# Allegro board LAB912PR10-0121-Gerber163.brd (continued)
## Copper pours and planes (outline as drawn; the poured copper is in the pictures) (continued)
SW_1.35VP on TOP: 61.84,41.3 64.64,41.3 64.89,41.04 64.89,33.1 64.38,32.6 59.81,32.6 59.62,32.79 59.62,37.99 59.81,38.18 61.72,38.18 61.78,38.25 61.78,41.23
SW_1.35VP on TOP: 59.33,49.04 60.09,49.04 60.3,48.83 60.3,48.75 60.7,48.34 60.7,46.19 60.64,46.12 60,46.12 59.94,46.19 59.94,47.65 59.23,48.35 59.23,48.95
UG_3V on TOP (solid shape): 37.2,46.31 37.2,46.12 36.19,45.11 35.55,45.11 35.43,45.23 35.43,45.61 36.19,46.38 37.14,46.38
UG_3V on TOP: 33.08,41.61 32.7,41.61 32.63,41.55 32.63,40.97 32.59,40.93 32.59,40.51 32.75,40.36 33.61,40.36 33.72,40.47 33.72,40.97
UG_3V on IN2: 32.63,41.55 32.63,40.34 32.74,40.24 33.51,40.24 33.71,40.43 33.71,41.68 33.65,41.74 32.82,41.74
UG_3V on IN2: 35.83,46.09 36.43,46.09 36.57,45.95 36.57,45.68 35.01,44.12 34.84,44.12 34.41,44.55 34.41,44.67
UG_5V on TOP (solid shape): 46.41,41.36 46.41,40.72 46.22,40.53 45.33,40.53 45.14,40.72 45.14,41.61 45.27,41.74 46.03,41.74
UG_5V on TOP: 40.65,45.55 40.52,45.42 39.69,45.42 39.5,45.61 39.5,45.99 39.38,46.12 39.38,46.3 39.45,46.38 40.29,46.38 40.65,46.02
UG_5V on IN2: 45.14,41.99 46.16,41.99 46.28,41.87 46.28,40.6 46.16,40.47 45.27,40.47 44.89,40.85 44.89,41.74
UG_5V on IN2: 41.32,46.15 41.48,45.98 41.48,45.31 41.31,45.13 40.75,45.13 40.37,45.51 39.48,45.51 39.41,45.57 39.41,45.89 39.67,46.15
UGATE1 on TOP: 135.06,135.21 135.12,135.28 135.12,136.74 135.06,136.8 133.98,136.8 133.91,136.74 133.91,135.28 133.98,135.21
UGATE1 on BOTTOM: 124.58,146.87 124.58,146.03 124.79,145.82 126.05,145.82 126.15,145.91 126.15,146.49 126.08,146.56 125.06,146.56 124.72,146.9 124.61,146.9
UGATE1 on IN2: 133.72,137.75 133.72,136.36 133.85,136.23 134.99,136.23 135.12,136.36 135.12,137.63 134.93,137.82 133.79,137.82
UGATE1 on IN2: 124.92,146.11 125.14,145.89 126.18,145.89 126.92,145.15 127.15,145.15 127.67,145.67 127.67,145.86 126.69,146.85 125.1,146.85 124.92,146.67
UGATE1-1 on TOP: 132.71,136.23 133.47,136.23 133.53,136.16 133.53,135.28 133.47,135.21 131.76,135.21 131.57,135.4 131.57,136.04 131.63,136.1 132.58,136.1
UGATEG1 on TOP: 118.8,139.02 117.79,139.02 117.72,139.09 117.72,140.29 117.79,140.36 118.87,140.36 118.93,140.29 118.93,139.15
UGATEG1 on BOTTOM: 120.89,147.2 121.67,147.2 121.73,147.14 121.73,146.97 121.31,146.55 120.56,145.8 120.37,145.8 120.04,146.13 120.04,146.35
UGATEG1 on IN2: 121.19,146.84 121.19,146.41 119.88,145.1 119.46,145.1 118.83,145.73 118.83,146.08 119.92,147.18 120.86,147.18
UGATEG1 on IN2: 117.79,141.24 117.79,139.91 117.91,139.78 118.99,139.78 119.12,139.91 119.12,141.18 118.93,141.37 117.91,141.37
UGATEG1-1 on TOP: 117.91,138.51 117.79,138.39 117.79,137.75 117.85,137.69 119.75,137.69 119.88,137.82 119.88,138.39 119.75,138.51
VGA_V1P35_S3_F1 on BOTTOM (solid shape): outline of 104 points within 114.79,107.31 119.75,112.46
N17188574 on TOP: 41.71,24.28 41.71,25.04 41.78,25.1 43.81,25.1 44.06,24.85 44.06,23.01 43.87,22.82 42.35,22.82 41.71,23.45 41.71,24.15 41.2,24.15 41.2,24.28
N17188613 on TOP: 45.65,24.85 47.68,24.85 47.81,24.72 47.81,23.96 47.68,23.83 45.65,23.83 45.52,23.96 45.52,24.72
N17227658 on BOTTOM (solid shape): 154.49,92.5 154.49,90.72 154.81,90.41 157.35,90.41 157.47,90.28 157.47,88.06 157.35,87.93 152.1,87.93 152.1,88.32 151.5,88.32 151.5,88.45 152.1,88.45 152.1,89.52 151.85,89.77 151.85,91.16 152.08,91.38 152.09,91.38 153.4,92.69 154.3,92.69
N17256593 on TOP: 59.24,34.76 57.27,34.76 57.14,34.63 57.14,33.99 57.21,33.93 57.97,33.93 58.1,33.8 58.1,32.91 58.22,32.79 59.24,32.79 59.37,32.91 59.37,34.63
N24334655 on BOTTOM (solid shape): 159.76,97.35 159.76,95.32 159.45,95.02 157.75,95.02 157.26,95.51 157.26,95.98 157.23,96.01 156.72,96.01 156.7,96.03 156.7,96.16 156.72,96.18 157.21,96.18 157.26,96.24 157.26,96.73 157.38,96.86 158.17,96.86 158.81,97.49 159.62,97.49
N24334673 on BOTTOM: 162.62,99.02 164.52,99.02 164.65,98.89 164.65,98.38 164.39,98.13 162.62,98.13 162.49,98.26 162.49,98.89
N24559749 on BOTTOM (solid shape): 153.26,115.88 153.26,113.85 153.17,113.76 152.57,113.76 152.36,113.98 151.24,113.98 151.15,113.89 151.15,113.43 151.14,113.42 151,113.42 150.97,113.44 150.97,113.95 150.95,113.98 150.34,113.98 150.18,114.13 150.18,115.97 150.29,116.07 153.06,116.07
N24559796 on BOTTOM: 156.27,117.56 158.17,117.56 158.3,117.43 158.3,116.8 158.17,116.67 156.27,116.67 156.14,116.8 156.14,117.43
N24654163 on TOP (solid shape): 33.46,47.75 33.46,45.69 33.36,45.59 32.8,45.59 32.7,45.69 32.7,47.77 32.77,47.85 33.36,47.85
N24654248 on TOP (solid shape): 43.87,47.77 43.87,45.61 43.81,45.55 43.17,45.55 43.11,45.61 43.11,47.77 43.17,47.84 43.81,47.84
N27376108 on TOP: 103.21,162.57 103.42,162.35 103.42,159.75 103.88,159.29 103.88,158.44 104.43,158.44 104.43,158 103.88,158 103.88,157.25 104.44,157.25 104.44,156.8 103.88,156.8 103.88,156.13 103.82,156.07 101.67,156.07 101.5,156.23 101.5,158.54 101.4,158.64 100.69,158.64 100.51,158.82 100.51,162.42 100.67,162.57
N28121198 on BOTTOM: 117.66,144.82 119.63,144.82 119.64,144.81 119.64,143.1 119.45,142.91 117.74,142.91 117.54,143.1 117.54,144.71
N100768097 on TOP: 128.33,134.7 126.87,134.7 126.55,134.39 126.55,133.82 126.61,133.75 128.2,133.75 128.39,133.94 128.39,134.64
N100768278 on TOP: 124.26,134.7 122.77,134.7 122.71,134.64 122.71,133.75 122.77,133.69 124.26,133.69 124.39,133.82 124.39,134.58
N100768460 on BOTTOM: 126.78,144.41 126.78,145.17 126.9,145.3 128.94,145.3 129.06,145.17 129.06,144.41 128.94,144.28 126.9,144.28

Small or netless copper shapes (teardrops, artwork), in the pictures only: 25 on TOP, 153 on BOTTOM, 8 on IN1, 2 on IN2

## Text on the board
Ref Des/Silkscreen Bottom: FAN | HDD | EDP | H12 | H11 | SODIMM-ONLY | SUPPORT DDR3L | H6 | H5 | M2X3L | H1
User.Comments: LA-B912P | AAL11 | 2015-01-20 | Rita | 2016-01-20 | 1.0(A00)
Ref Des/Silkscreen Top: IO | TP | KB | PWR | ODD
COMPVAL_TYPE_TOP: FIGURE | SIZE | 8.0 | 22.0 | 28.0 | 39.0 | 118.0 | 126.0 | 130.0 | 31.0 | 43.0 | 47.0 | 55.0 | 63.0 | 67.0 | 157.0 | 63.0x28.0 | 67.0x35.0 | 94.0x28.0 | 94.0x35.0 | 112.0x31.0 | 134.0x24.0 | 150.0x118.0 | DRILL CHART: TOP to BOTTOM | ALL UNITS ARE IN MILS | TOLERANCE | +3.0/-3.0 | +2.0/-2.0 | PLATED | NON-PLATED | QTY | 3086 | 19 | 9 | 8 | 4 | 1 | 2
